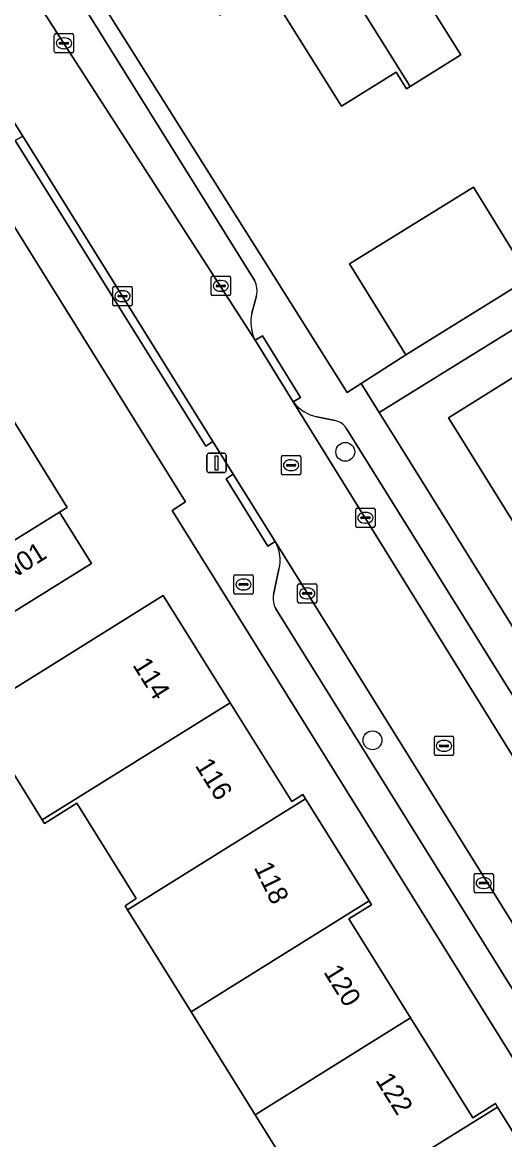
# Model space of a CAD drawing. Extents: x 159352 to 160617, y 385888 to 387323.
# Drawn here: x 159676 to 159701, y 385971 to 386029 of the extents above; entities that cross this region are included whole.
import ezdxf

# ---------------------------------------------------------------- set-up
doc = ezdxf.new("R2010")
doc.units = 0
for name, color, linetype in [('IMGEO_Boom', 7, 'Continuous'), ('IMGEO_Brandkraan', 7, 'Continuous'), ('IMGEO_Erf', 7, 'Continuous'), ('IMGEO_Kolk', 7, 'Continuous'), ('IMGEO_Lichtmast', 7, 'Continuous'), ('IMGEO_Muur', 7, 'Continuous'), ('IMGEO_Pand', 7, 'Continuous'), ('IMGEO_Pand_nummerreeks', 7, 'Continuous'), ('IMGEO_Parkeervlak_open', 7, 'Continuous'), ('IMGEO_Rijbaan_lokaal_open', 7, 'Continuous'), ('IMGEO_Rioolput', 7, 'Continuous'), ('IMGEO_Voetpad_open', 7, 'Continuous')]:
    doc.layers.add(name, color=color, linetype=linetype)

msp = doc.modelspace()

# ---------------------------------------------------------------- linework, layer by layer
at = {"layer": 'IMGEO_Boom'}
for centre in [(159692.77, 386006.677), (159694.18, 385991.71)]:
    msp.add_circle(centre, 0.489, dxfattribs=at)
at = {"layer": 'IMGEO_Brandkraan'}
for p, q in [((159687.056, 386000.294), (159687.908, 386000.294)), ((159686.981, 385999.368), (159686.981, 386000.22)), ((159687.24, 385999.788), (159687.24, 385999.8)), ((159687.678, 385999.751), (159687.28, 385999.751)), ((159687.283, 385999.837), (159687.681, 385999.837)), ((159687.469, 386000.074), (159687.494, 386000.074)), ((159687.724, 385999.8), (159687.724, 385999.788)), ((159687.982, 386000.22), (159687.982, 385999.368)), ((159687.908, 385999.294), (159687.056, 385999.294)), ((159687.492, 385999.514), (159687.467, 385999.514))]:
    msp.add_line(p, q, dxfattribs=at)
for points in [[(159687.056, 386000.294), (159687.908, 386000.294)], [(159686.981, 385999.368), (159686.981, 386000.22)], [(159687.982, 386000.22), (159687.982, 385999.368)], [(159687.908, 385999.294), (159687.056, 385999.294)]]:
    msp.add_lwpolyline(points, dxfattribs=at)
for centre, radius, start, end in [((159687.058, 386000.218), 0.0765, 91.55205, 178.44795), ((159687.058, 386000.218), 0.0765, 91.55205, 178.44795), ((159687.906, 386000.218), 0.0765, 1.55205, 88.44795), ((159687.906, 386000.218), 0.0765, 1.55205, 88.44795), ((159687.28, 385999.797), 0.0403, 85.87752, 175.75265), ((159687.277, 385999.787), 0.0366, 178.93798, 274.71019), ((159687.681, 385999.794), 0.043, 264.86636, 352.45326), ((159687.685, 385999.799), 0.0386, 1.73085, 96.63898), ((159687.058, 385999.37), 0.0765, 181.55205, 268.44795), ((159687.058, 385999.37), 0.0765, 181.55205, 268.44795), ((159687.906, 385999.37), 0.0765, 271.55205, 358.44795), ((159687.906, 385999.37), 0.0765, 271.55205, 358.44795)]:
    msp.add_arc(centre, radius, start, end, dxfattribs=at)
for centre, major_axis, ratio, start_param, end_param in [((159687.468, 385999.794), (-0.387, 0.002), 0.722429, 4.712389, 7.853982), ((159687.493, 385999.794), (-0.39, 0.002), 0.717154, 1.570796, 4.712389)]:
    msp.add_ellipse(centre, major_axis=major_axis, ratio=ratio, start_param=start_param, end_param=end_param, dxfattribs=at)
at = {"layer": 'IMGEO_Erf'}
for points in [[(159733.186, 386035.211), (159730.405, 386039.383), (159739.998, 386045.377), (159726.053, 386067.427), (159724.652, 386067.823), (159682.76, 386041.661), (159677.195, 386038.177), (159676.499, 386035.726), (159692.861, 386009.756), (159693.588, 386010.224), (159695.905, 386011.714), (159692.99, 386016.431), (159699.422, 386020.406), (159702.337, 386015.688), (159707.722, 386019.015), (159705.988, 386021.823), (159710.701, 386024.734), (159712.435, 386021.927)], [(159701.573, 386002.905), (159698.121, 386008.449), (159712.358, 386017.329), (159711.277, 386019.075), (159694.532, 386008.709), (159695.653, 386006.911), (159722.539, 385963.769), (159725.011, 385965.31), (159721.556, 385970.854), (159718.347, 385976.003), (159717.769, 385975.633), (159717.641, 385975.838), (159714.307, 385981.183), (159714.197, 385981.36), (159715.376, 385982.096), (159712.158, 385987.259), (159708.951, 385992.406), (159707.766, 385991.665), (159707.64, 385991.867), (159704.315, 385997.19), (159704.197, 385997.379), (159704.777, 385997.76)], [(159665.523, 386010.882), (159671.584, 386014.653), (159678.317, 386003.795), (159677.918, 386003.547), (159679.586, 386000.875), (159674.257, 385997.571), (159672.593, 386000.246), (159672.266, 386000.043)]]:
    msp.add_lwpolyline(points, close=True, dxfattribs=at)
for points in [[(159726.677, 385934.766), (159683.777, 386003.638), (159684.463, 386004.075), (159676.127, 386017.48), (159664.396, 386036.344)], [(159694.342, 386034.344), (159698.765, 386027.275), (159696.144, 386025.636), (159695.953, 386025.516), (159695.412, 386026.381), (159692.572, 386024.604), (159688.668, 386030.843)], [(159669.077, 385990.354), (159683.311, 385999.215), (159686.788, 385993.654), (159689.987, 385988.537), (159690.57, 385988.891), (159690.706, 385988.673), (159694.003, 385983.38), (159694.133, 385983.172), (159692.958, 385982.44), (159696.161, 385977.302), (159699.391, 385972.121), (159700.565, 385972.856), (159700.666, 385972.682), (159703.999, 385967.336)], [(159691.427, 385966.923), (159688.093, 385972.273), (159684.76, 385977.619), (159681.462, 385982.911), (159681.327, 385983.127), (159681.915, 385983.494), (159678.832, 385988.443), (159677.142, 385987.397), (159677.032, 385987.574), (159675.262, 385990.432)]]:
    msp.add_lwpolyline(points, dxfattribs=at)
at = {"layer": 'IMGEO_Kolk'}
for p, q in [((159677.656, 386027.449), (159677.656, 386028.301)), ((159677.731, 386028.375), (159678.583, 386028.375)), ((159678.144, 386028.155), (159678.169, 386028.155)), ((159678.657, 386028.301), (159678.657, 386027.449)), ((159677.915, 386027.869), (159677.915, 386027.881)), ((159678.353, 386027.832), (159677.955, 386027.832)), ((159677.958, 386027.918), (159678.356, 386027.918)), ((159678.167, 386027.595), (159678.142, 386027.595)), ((159678.399, 386027.881), (159678.399, 386027.869)), ((159678.583, 386027.375), (159677.731, 386027.375)), ((159685.802, 386014.862), (159685.802, 386015.714)), ((159685.877, 386015.788), (159686.729, 386015.788)), ((159686.104, 386015.331), (159686.502, 386015.331)), ((159686.29, 386015.568), (159686.315, 386015.568)), ((159686.803, 386015.714), (159686.803, 386014.862)), ((159680.697, 386014.328), (159680.697, 386015.18)), ((159680.772, 386015.254), (159681.624, 386015.254)), ((159680.956, 386014.748), (159680.956, 386014.76)), ((159680.999, 386014.797), (159681.397, 386014.797)), ((159681.185, 386015.034), (159681.21, 386015.034)), ((159681.44, 386014.76), (159681.44, 386014.748)), ((159681.698, 386015.18), (159681.698, 386014.328)), ((159686.729, 386014.788), (159685.877, 386014.788)), ((159686.061, 386015.282), (159686.061, 386015.294)), ((159686.499, 386015.245), (159686.101, 386015.245)), ((159686.313, 386015.008), (159686.288, 386015.008)), ((159686.545, 386015.294), (159686.545, 386015.282)), ((159681.624, 386014.254), (159680.772, 386014.254)), ((159681.394, 386014.711), (159680.996, 386014.711)), ((159681.208, 386014.474), (159681.183, 386014.474)), ((159693.387, 386003.757), (159694.239, 386003.757)), ((159693.312, 386002.831), (159693.312, 386003.683)), ((159693.571, 386003.251), (159693.571, 386003.263)), ((159694.009, 386003.214), (159693.611, 386003.214)), ((159693.614, 386003.3), (159694.012, 386003.3)), ((159693.8, 386003.537), (159693.825, 386003.537)), ((159694.055, 386003.263), (159694.055, 386003.251)), ((159694.313, 386003.683), (159694.313, 386002.831)), ((159694.239, 386002.757), (159693.387, 386002.757)), ((159693.823, 386002.977), (159693.798, 386002.977)), ((159690.291, 385998.907), (159690.291, 385999.759)), ((159690.366, 385999.833), (159691.218, 385999.833)), ((159691.292, 385999.759), (159691.292, 385998.907)), ((159690.55, 385999.327), (159690.55, 385999.339)), ((159690.988, 385999.29), (159690.59, 385999.29)), ((159690.593, 385999.376), (159690.991, 385999.376)), ((159690.779, 385999.613), (159690.804, 385999.613)), ((159691.034, 385999.339), (159691.034, 385999.327)), ((159691.218, 385998.833), (159690.366, 385998.833)), ((159690.802, 385999.053), (159690.777, 385999.053)), ((159699.461, 385983.876), (159699.461, 385984.728)), ((159699.536, 385984.802), (159700.388, 385984.802)), ((159700.462, 385984.728), (159700.462, 385983.876)), ((159699.72, 385984.296), (159699.72, 385984.308)), ((159700.158, 385984.259), (159699.76, 385984.259)), ((159699.763, 385984.345), (159700.161, 385984.345)), ((159699.972, 385984.022), (159699.947, 385984.022)), ((159699.949, 385984.582), (159699.974, 385984.582)), ((159700.204, 385984.308), (159700.204, 385984.296)), ((159700.388, 385983.802), (159699.536, 385983.802))]:
    msp.add_line(p, q, dxfattribs=at)
for points in [[(159677.656, 386027.449), (159677.656, 386028.301)], [(159677.731, 386028.375), (159678.583, 386028.375)], [(159678.657, 386028.301), (159678.657, 386027.449)], [(159678.583, 386027.375), (159677.731, 386027.375)], [(159685.802, 386014.862), (159685.802, 386015.714)], [(159685.877, 386015.788), (159686.729, 386015.788)], [(159686.803, 386015.714), (159686.803, 386014.862)], [(159680.697, 386014.328), (159680.697, 386015.18)], [(159680.772, 386015.254), (159681.624, 386015.254)], [(159681.698, 386015.18), (159681.698, 386014.328)], [(159686.729, 386014.788), (159685.877, 386014.788)], [(159681.624, 386014.254), (159680.772, 386014.254)], [(159693.387, 386003.757), (159694.239, 386003.757)], [(159693.312, 386002.831), (159693.312, 386003.683)], [(159694.313, 386003.683), (159694.313, 386002.831)], [(159694.239, 386002.757), (159693.387, 386002.757)], [(159690.291, 385998.907), (159690.291, 385999.759)], [(159690.366, 385999.833), (159691.218, 385999.833)], [(159691.292, 385999.759), (159691.292, 385998.907)], [(159691.218, 385998.833), (159690.366, 385998.833)], [(159699.461, 385983.876), (159699.461, 385984.728)], [(159699.536, 385984.802), (159700.388, 385984.802)], [(159700.462, 385984.728), (159700.462, 385983.876)], [(159700.388, 385983.802), (159699.536, 385983.802)]]:
    msp.add_lwpolyline(points, dxfattribs=at)
for centre, radius, start, end in [((159677.733, 386028.299), 0.0765, 91.55205, 178.44795), ((159677.733, 386028.299), 0.0765, 91.55205, 178.44795), ((159678.581, 386028.299), 0.0765, 1.55205, 88.44795), ((159678.581, 386028.299), 0.0765, 1.55205, 88.44795), ((159677.955, 386027.878), 0.0403, 85.87752, 175.75265), ((159677.952, 386027.868), 0.0366, 178.93798, 274.71019), ((159678.356, 386027.875), 0.043, 264.86636, 352.45326), ((159678.36, 386027.88), 0.0386, 1.73085, 96.63898), ((159677.733, 386027.451), 0.0765, 181.55205, 268.44795), ((159677.733, 386027.451), 0.0765, 181.55205, 268.44795), ((159678.581, 386027.451), 0.0765, 271.55205, 358.44795), ((159678.581, 386027.451), 0.0765, 271.55205, 358.44795), ((159685.879, 386015.712), 0.0765, 91.55205, 178.44795), ((159685.879, 386015.712), 0.0765, 91.55205, 178.44795), ((159686.101, 386015.291), 0.0403, 85.87752, 175.75265), ((159686.506, 386015.293), 0.0386, 1.73085, 96.63898), ((159686.727, 386015.712), 0.0765, 1.55205, 88.44795), ((159686.727, 386015.712), 0.0765, 1.55205, 88.44795), ((159680.774, 386015.178), 0.0765, 91.55205, 178.44795), ((159680.774, 386015.178), 0.0765, 91.55205, 178.44795), ((159680.996, 386014.757), 0.0403, 85.87752, 175.75265), ((159680.993, 386014.747), 0.0366, 178.93798, 274.71019), ((159681.397, 386014.754), 0.043, 264.86636, 352.45326), ((159681.401, 386014.759), 0.0386, 1.73085, 96.63898), ((159681.622, 386015.178), 0.0765, 1.55205, 88.44795), ((159681.622, 386015.178), 0.0765, 1.55205, 88.44795), ((159685.879, 386014.864), 0.0765, 181.55205, 268.44795), ((159685.879, 386014.864), 0.0765, 181.55205, 268.44795), ((159686.098, 386015.281), 0.0366, 178.93798, 274.71019), ((159686.502, 386015.288), 0.043, 264.86636, 352.45326), ((159686.727, 386014.864), 0.0765, 271.55205, 358.44795), ((159686.727, 386014.864), 0.0765, 271.55205, 358.44795), ((159680.774, 386014.33), 0.0765, 181.55205, 268.44795), ((159680.774, 386014.33), 0.0765, 181.55205, 268.44795), ((159681.622, 386014.33), 0.0765, 271.55205, 358.44795), ((159681.622, 386014.33), 0.0765, 271.55205, 358.44795), ((159693.389, 386003.681), 0.0765, 91.55205, 178.44795), ((159693.389, 386003.681), 0.0765, 91.55205, 178.44795), ((159694.237, 386003.681), 0.0765, 1.55205, 88.44795), ((159694.237, 386003.681), 0.0765, 1.55205, 88.44795), ((159693.611, 386003.26), 0.0403, 85.87752, 175.75265), ((159693.608, 386003.25), 0.0366, 178.93798, 274.71019), ((159694.012, 386003.257), 0.043, 264.86636, 352.45326), ((159694.016, 386003.262), 0.0386, 1.73085, 96.63898), ((159693.389, 386002.833), 0.0765, 181.55205, 268.44795), ((159693.389, 386002.833), 0.0765, 181.55205, 268.44795), ((159694.237, 386002.833), 0.0765, 271.55205, 358.44795), ((159694.237, 386002.833), 0.0765, 271.55205, 358.44795), ((159690.368, 385999.757), 0.0765, 91.55205, 178.44795), ((159690.368, 385999.757), 0.0765, 91.55205, 178.44795), ((159691.216, 385999.757), 0.0765, 1.55205, 88.44795), ((159691.216, 385999.757), 0.0765, 1.55205, 88.44795), ((159690.59, 385999.336), 0.0403, 85.87752, 175.75265), ((159690.587, 385999.326), 0.0366, 178.93798, 274.71019), ((159690.991, 385999.333), 0.043, 264.86636, 352.45326), ((159690.995, 385999.338), 0.0386, 1.73085, 96.63898), ((159690.368, 385998.909), 0.0765, 181.55205, 268.44795), ((159690.368, 385998.909), 0.0765, 181.55205, 268.44795), ((159691.216, 385998.909), 0.0765, 271.55205, 358.44795), ((159691.216, 385998.909), 0.0765, 271.55205, 358.44795), ((159699.538, 385984.726), 0.0765, 91.55205, 178.44795), ((159699.538, 385984.726), 0.0765, 91.55205, 178.44795), ((159700.386, 385984.726), 0.0765, 1.55205, 88.44795), ((159700.386, 385984.726), 0.0765, 1.55205, 88.44795), ((159699.76, 385984.305), 0.0403, 85.87752, 175.75265), ((159699.757, 385984.295), 0.0366, 178.93798, 274.71019), ((159700.161, 385984.302), 0.043, 264.86636, 352.45326), ((159700.165, 385984.307), 0.0386, 1.73085, 96.63898), ((159699.538, 385983.878), 0.0765, 181.55205, 268.44795), ((159699.538, 385983.878), 0.0765, 181.55205, 268.44795), ((159700.386, 385983.878), 0.0765, 271.55205, 358.44795), ((159700.386, 385983.878), 0.0765, 271.55205, 358.44795)]:
    msp.add_arc(centre, radius, start, end, dxfattribs=at)
for centre, major_axis, ratio, start_param, end_param in [((159678.143, 386027.875), (-0.387, 0.002), 0.722429, 4.712389, 7.853982), ((159678.168, 386027.875), (-0.39, 0.002), 0.717154, 1.570796, 4.712389), ((159686.289, 386015.288), (-0.387, 0.002), 0.722429, 4.712389, 7.853982), ((159686.314, 386015.288), (-0.39, 0.002), 0.717154, 1.570796, 4.712389), ((159681.184, 386014.754), (-0.387, 0.002), 0.722429, 4.712389, 7.853982), ((159681.209, 386014.754), (-0.39, 0.002), 0.717154, 1.570796, 4.712389), ((159693.799, 386003.257), (-0.387, 0.002), 0.722429, 4.712389, 7.853982), ((159693.824, 386003.257), (-0.39, 0.002), 0.717154, 1.570796, 4.712389), ((159690.778, 385999.333), (-0.387, 0.002), 0.722429, 4.712389, 7.853982), ((159690.803, 385999.333), (-0.39, 0.002), 0.717154, 1.570796, 4.712389), ((159699.948, 385984.302), (-0.387, 0.002), 0.722429, 4.712389, 7.853982), ((159699.973, 385984.302), (-0.39, 0.002), 0.717154, 1.570796, 4.712389)]:
    msp.add_ellipse(centre, major_axis=major_axis, ratio=ratio, start_param=start_param, end_param=end_param, dxfattribs=at)
at = {"layer": 'IMGEO_Lichtmast'}
for p, q in [((159685.584, 386005.702), (159685.584, 386006.502)), ((159685.584, 386006.502), (159685.584, 386005.702)), ((159685.684, 386006.602), (159686.474, 386006.602)), ((159686.474, 386006.602), (159685.684, 386006.602)), ((159686.574, 386006.502), (159686.574, 386005.702)), ((159686.574, 386005.702), (159686.574, 386006.502)), ((159686.474, 386005.602), (159685.684, 386005.602)), ((159685.684, 386005.602), (159686.474, 386005.602))]:
    msp.add_line(p, q, dxfattribs=at)
msp.add_lwpolyline([(159686.004, 386006.477), (159686.154, 386006.477), (159686.154, 386005.727), (159686.004, 386005.727), (159686.004, 386006.477)], dxfattribs=at)
for centre, start, end in [((159685.684, 386006.502), 90, 180), ((159685.684, 386006.502), 90, 180), ((159686.474, 386006.502), 0, 90), ((159686.474, 386006.502), 360, 90), ((159685.684, 386005.702), 180, 270), ((159685.684, 386005.702), 180, 270), ((159686.474, 386005.702), 270, 0), ((159686.474, 386005.702), 270, 0)]:
    msp.add_arc(centre, 0.1, start, end, dxfattribs=at)
at = {"layer": 'IMGEO_Muur'}
msp.add_lwpolyline([(159676.499, 386035.726), (159692.838, 386009.794)], dxfattribs=at)
at = {"layer": 'IMGEO_Pand'}
for points in [[(159692.982, 386042.203), (159687.801, 386038.964), (159696.144, 386025.636), (159698.765, 386027.275), (159694.342, 386034.344), (159696.906, 386035.948)], [(159687.801, 386038.964), (159682.354, 386035.559), (159686.251, 386029.331), (159688.668, 386030.843), (159692.572, 386024.604), (159695.412, 386026.381), (159695.953, 386025.516), (159696.144, 386025.636)], [(159702.337, 386015.688), (159699.422, 386020.406), (159692.99, 386016.431), (159695.905, 386011.714)], [(159709.58, 386011.831), (159714.064, 386014.619), (159713.852, 386014.956), (159712.358, 386017.329), (159698.121, 386008.449), (159701.573, 386002.905), (159711.345, 386008.993)], [(159678.317, 386003.795), (159671.584, 386014.653), (159665.523, 386010.882), (159672.266, 386000.043), (159672.593, 386000.246), (159677.918, 386003.547)], [(159674.257, 385997.571), (159679.586, 386000.875), (159677.918, 386003.547), (159672.593, 386000.246)], [(159686.788, 385993.654), (159683.311, 385999.215), (159669.077, 385990.354), (159670.756, 385987.642), (159675.262, 385990.432), (159677.032, 385987.574)], [(159690.706, 385988.673), (159690.57, 385988.891), (159689.987, 385988.537), (159686.788, 385993.654), (159677.032, 385987.574), (159677.142, 385987.397), (159678.832, 385988.443), (159681.915, 385983.494), (159681.327, 385983.127), (159681.462, 385982.911)], [(159681.462, 385982.911), (159684.76, 385977.619), (159694.003, 385983.38), (159690.706, 385988.673)], [(159696.161, 385977.302), (159692.958, 385982.44), (159694.133, 385983.172), (159694.003, 385983.38), (159684.76, 385977.619), (159688.093, 385972.273)], [(159688.093, 385972.273), (159691.427, 385966.923), (159700.666, 385972.682), (159700.565, 385972.856), (159699.391, 385972.121), (159696.161, 385977.302)], [(159703.999, 385967.336), (159700.666, 385972.682), (159691.427, 385966.923), (159694.759, 385961.577)]]:
    msp.add_lwpolyline(points, close=True, dxfattribs=at)
at = {"layer": 'IMGEO_Parkeervlak_open'}
for points in [[(159676.243, 386030.847), (159688.08, 386012.469)], [(159688.07, 386015.556), (159679.356, 386029.499)], [(159687.917, 386013.868), (159688.156, 386014.778)], [(159690.064, 386009.27), (159733.253, 385939.657)], [(159692.239, 386008.296), (159691.296, 386008.497)], [(159721.084, 385962.578), (159692.854, 386007.849)], [(159729.51, 385937.17), (159689.128, 386002.021)], [(159689.324, 386000.58), (159689.045, 385999.275)], [(159689.162, 385998.525), (159714.229, 385958.291)]]:
    msp.add_lwpolyline(points, dxfattribs=at)
for centre, radius, start, end in [((159686.999, 386015.044), 1.187, 347.05822, 25.55749), ((159689.968, 386013.398), 2.104, 167.08889, 206.20245), ((159691.683, 386010.482), 2.023, 216.822, 258.9668), ((159692.055, 386007.396), 0.919, 29.55542, 78.42308), ((159687.521, 386001.069), 1.868, 344.84268, 30.64862), ((159690.038, 385999.046), 1.019, 166.9962, 210.73715)]:
    msp.add_arc(centre, radius, start, end, dxfattribs=at)
at = {"layer": 'IMGEO_Rijbaan_lokaal_open'}
msp.add_lwpolyline([(159729.606, 385937.026), (159733.392, 385939.433), (159733.253, 385939.657), (159690.064, 386009.27), (159688.08, 386012.469), (159676.243, 386030.847), (159672.6, 386028.467), (159676.012, 386023.063), (159685.883, 386007.217), (159686.951, 386005.519), (159689.128, 386002.021), (159729.51, 385937.17)], close=True, dxfattribs=at)
at = {"layer": 'IMGEO_Rioolput'}
for p, q in [((159689.454, 386005.557), (159689.454, 386006.409)), ((159689.529, 386006.483), (159690.381, 386006.483)), ((159689.942, 386006.263), (159689.967, 386006.263)), ((159690.455, 386006.409), (159690.455, 386005.557)), ((159690.381, 386005.483), (159689.529, 386005.483)), ((159689.713, 386005.977), (159689.713, 386005.989)), ((159690.151, 386005.94), (159689.753, 386005.94)), ((159689.756, 386006.026), (159690.154, 386006.026)), ((159689.965, 386005.703), (159689.94, 386005.703)), ((159690.197, 386005.989), (159690.197, 386005.977)), ((159697.394, 385990.995), (159697.394, 385991.847)), ((159697.469, 385991.921), (159698.321, 385991.921)), ((159697.882, 385991.701), (159697.907, 385991.701)), ((159698.395, 385991.847), (159698.395, 385990.995)), ((159697.653, 385991.415), (159697.653, 385991.427)), ((159698.091, 385991.378), (159697.693, 385991.378)), ((159697.696, 385991.464), (159698.094, 385991.464)), ((159697.905, 385991.141), (159697.88, 385991.141)), ((159698.137, 385991.427), (159698.137, 385991.415)), ((159698.321, 385990.921), (159697.469, 385990.921))]:
    msp.add_line(p, q, dxfattribs=at)
for points in [[(159689.454, 386005.557), (159689.454, 386006.409)], [(159689.529, 386006.483), (159690.381, 386006.483)], [(159690.455, 386006.409), (159690.455, 386005.557)], [(159690.381, 386005.483), (159689.529, 386005.483)], [(159697.394, 385990.995), (159697.394, 385991.847)], [(159697.469, 385991.921), (159698.321, 385991.921)], [(159698.395, 385991.847), (159698.395, 385990.995)], [(159698.321, 385990.921), (159697.469, 385990.921)]]:
    msp.add_lwpolyline(points, dxfattribs=at)
for centre, radius, start, end in [((159689.531, 386006.407), 0.0765, 91.55205, 178.44795), ((159689.531, 386006.407), 0.0765, 91.55205, 178.44795), ((159690.379, 386006.407), 0.0765, 1.55205, 88.44795), ((159690.379, 386006.407), 0.0765, 1.55205, 88.44795), ((159689.531, 386005.559), 0.0765, 181.55205, 268.44795), ((159689.531, 386005.559), 0.0765, 181.55205, 268.44795), ((159689.753, 386005.986), 0.0403, 85.87752, 175.75265), ((159689.75, 386005.976), 0.0366, 178.93798, 274.71019), ((159690.154, 386005.983), 0.043, 264.86636, 352.45326), ((159690.158, 386005.988), 0.0386, 1.73085, 96.63898), ((159690.379, 386005.559), 0.0765, 271.55205, 358.44795), ((159690.379, 386005.559), 0.0765, 271.55205, 358.44795), ((159697.471, 385991.845), 0.0765, 91.55205, 178.44795), ((159697.471, 385991.845), 0.0765, 91.55205, 178.44795), ((159698.319, 385991.845), 0.0765, 1.55205, 88.44795), ((159698.319, 385991.845), 0.0765, 1.55205, 88.44795), ((159697.471, 385990.997), 0.0765, 181.55205, 268.44795), ((159697.471, 385990.997), 0.0765, 181.55205, 268.44795), ((159697.693, 385991.424), 0.0403, 85.87752, 175.75265), ((159697.69, 385991.414), 0.0366, 178.93798, 274.71019), ((159698.094, 385991.421), 0.043, 264.86636, 352.45326), ((159698.098, 385991.426), 0.0386, 1.73085, 96.63898), ((159698.319, 385990.997), 0.0765, 271.55205, 358.44795), ((159698.319, 385990.997), 0.0765, 271.55205, 358.44795)]:
    msp.add_arc(centre, radius, start, end, dxfattribs=at)
for centre, major_axis, ratio, start_param, end_param in [((159689.941, 386005.983), (-0.387, 0.002), 0.722429, 4.712389, 7.853982), ((159689.966, 386005.983), (-0.39, 0.002), 0.717154, 1.570796, 4.712389), ((159697.881, 385991.421), (-0.387, 0.002), 0.722429, 4.712389, 7.853982), ((159697.906, 385991.421), (-0.39, 0.002), 0.717154, 1.570796, 4.712389)]:
    msp.add_ellipse(centre, major_axis=major_axis, ratio=ratio, start_param=start_param, end_param=end_param, dxfattribs=at)
at = {"layer": 'IMGEO_Voetpad_open'}
for points in [[(159669.792, 386033.391), (159665.503, 386040.276), (159667.526, 386041.555), (159666.211, 386043.692), (159665.019, 386042.984), (159664.447, 386037.85), (159664.396, 386036.344), (159676.127, 386017.48), (159684.463, 386004.075), (159683.777, 386003.638), (159726.677, 385934.766), (159729.867, 385936.632), (159729.606, 385937.026), (159729.51, 385937.17)], [(159733.253, 385939.657), (159733.392, 385939.433), (159733.652, 385939.014), (159736.793, 385940.979), (159724.622, 385960.426), (159722.539, 385963.769), (159695.653, 386006.911), (159694.532, 386008.709), (159693.588, 386010.224), (159692.861, 386009.756), (159676.499, 386035.726)], [(159689.128, 386002.021), (159688.743, 386001.782), (159686.576, 386005.278), (159686.951, 386005.519), (159685.883, 386007.217), (159685.522, 386006.976), (159675.629, 386022.83), (159676.012, 386023.063), (159672.6, 386028.467), (159670.612, 386031.633)], [(159679.356, 386029.499), (159688.07, 386015.556)], [(159688.156, 386014.778), (159687.917, 386013.868)], [(159688.08, 386012.469), (159688.466, 386012.689), (159690.446, 386009.495), (159690.064, 386009.27)], [(159691.296, 386008.497), (159692.239, 386008.296)], [(159692.854, 386007.849), (159721.084, 385962.578), (159721.452, 385962.783), (159723.277, 385959.824), (159722.95, 385959.611), (159733.348, 385942.906)], [(159689.045, 385999.275), (159689.324, 386000.58)], [(159726.497, 385938.638), (159716.071, 385955.325), (159715.692, 385955.092), (159713.835, 385958.065), (159714.229, 385958.291), (159689.162, 385998.525)]]:
    msp.add_lwpolyline(points, dxfattribs=at)
for points in [[(159743.822, 386039.222), (159742.641, 386041.129), (159733.186, 386035.211), (159712.435, 386021.927), (159707.722, 386019.015), (159702.337, 386015.688), (159695.905, 386011.714), (159693.588, 386010.224), (159694.532, 386008.709), (159711.277, 386019.075)], [(159676.012, 386023.063), (159675.629, 386022.83), (159685.522, 386006.976), (159685.883, 386007.217)], [(159690.064, 386009.27), (159690.446, 386009.495), (159688.466, 386012.689), (159688.08, 386012.469)], [(159689.128, 386002.021), (159686.951, 386005.519), (159686.576, 386005.278), (159688.743, 386001.782)]]:
    msp.add_lwpolyline(points, close=True, dxfattribs=at)
for centre, radius, start, end in [((159686.999, 386015.044), 1.187, 347.05822, 25.55749), ((159689.968, 386013.398), 2.104, 167.08889, 206.20245), ((159691.683, 386010.482), 2.023, 216.822, 258.9668), ((159692.055, 386007.396), 0.919, 29.55542, 78.42308), ((159687.521, 386001.069), 1.868, 344.84268, 30.64862), ((159690.038, 385999.046), 1.019, 166.9962, 210.73715)]:
    msp.add_arc(centre, radius, start, end, dxfattribs=at)

# ---------------------------------------------------------------- texts
at = {"layer": 'IMGEO_Pand_nummerreeks'}
for s, rotation, p in [('112/N01', 32.16888, (159673.061, 385998.516)), ('114', 302.01496, (159681.693, 385995.616)), ('116', 301.92235, (159684.938, 385990.401)), ('118', 295.96443, (159688.007, 385985.115)), ('120', 301.92235, (159691.612, 385979.687)), ('122', 301.94006, (159694.308, 385974.075))]:
    msp.add_text(s, height=1, rotation=rotation, dxfattribs=at).set_placement(p)

doc.saveas('drawing.dxf')
